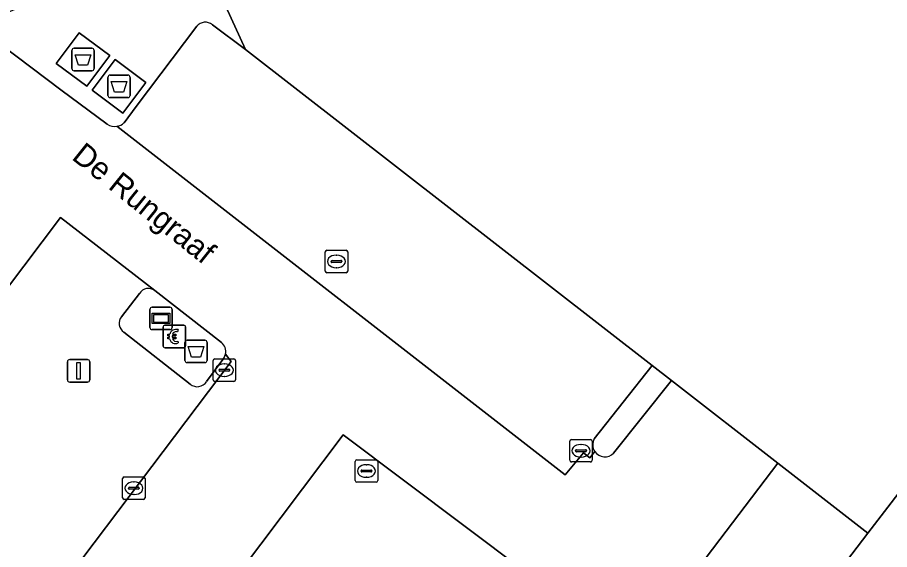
# Model space of a CAD drawing. Extents: x 160663 to 161506, y 382245 to 383291.
# Drawn here: x 161027.46 to 161066.28, y 382872.88 to 382896.55 of the extents above; entities that cross this region are included whole.
import ezdxf

# ---------------------------------------------------------------- set-up
doc = ezdxf.new("R2010")
doc.units = 0
for name, color, linetype in [('IMGEO_Afval_apart_plaats', 7, 'Continuous'), ('IMGEO_Afvalbak', 7, 'Continuous'), ('IMGEO_Betaalautomaat', 7, 'Continuous'), ('IMGEO_Erf', 7, 'Continuous'), ('IMGEO_Hek', 7, 'Continuous'), ('IMGEO_Kolk', 7, 'Continuous'), ('IMGEO_Lichtmast', 7, 'Continuous'), ('IMGEO_Muur', 7, 'Continuous'), ('IMGEO_Openbare_ruimte_label', 7, 'Continuous'), ('IMGEO_Parkeervlak_open', 7, 'Continuous'), ('IMGEO_Rijbaan_lokaal_open', 7, 'Continuous'), ('IMGEO_Rioolput', 7, 'Continuous'), ('IMGEO_Verkeerseiland_open', 7, 'Continuous'), ('IMGEO_Voetpad_gesloten', 7, 'Continuous'), ('IMGEO_Voetpad_open', 7, 'Continuous'), ('IMGEO_Wegwijzer', 7, 'Continuous')]:
    doc.layers.add(name, color=color, linetype=linetype)

msp = doc.modelspace()

# ---------------------------------------------------------------- linework, layer by layer
at = {"layer": 'IMGEO_Afval_apart_plaats'}
for p, q in [((161029.884, 382894.283), (161029.884, 382895.083)), ((161029.884, 382895.083), (161029.884, 382894.283)), ((161029.984, 382895.183), (161030.774, 382895.183)), ((161030.774, 382895.183), (161029.984, 382895.183)), ((161030.874, 382895.083), (161030.874, 382894.283)), ((161030.874, 382894.283), (161030.874, 382895.083)), ((161030.774, 382894.183), (161029.984, 382894.183)), ((161029.984, 382894.183), (161030.774, 382894.183)), ((161031.486, 382893.086), (161031.486, 382893.886)), ((161031.486, 382893.886), (161031.486, 382893.086)), ((161031.586, 382893.986), (161032.376, 382893.986)), ((161032.376, 382893.986), (161031.586, 382893.986)), ((161032.476, 382893.886), (161032.476, 382893.086)), ((161032.476, 382893.086), (161032.476, 382893.886)), ((161032.376, 382892.986), (161031.586, 382892.986)), ((161031.586, 382892.986), (161032.376, 382892.986))]:
    msp.add_line(p, q, dxfattribs=at)
for points in [[(161030.027, 382894.897), (161030.731, 382894.897), (161030.582, 382894.427), (161030.176, 382894.427), (161030.027, 382894.897)], [(161031.629, 382893.7), (161032.333, 382893.7), (161032.184, 382893.23), (161031.778, 382893.23), (161031.629, 382893.7)]]:
    msp.add_lwpolyline(points, dxfattribs=at)
for centre, start, end in [((161029.984, 382895.083), 90, 180), ((161029.984, 382895.083), 90, 180), ((161030.774, 382895.083), 0, 90), ((161030.774, 382895.083), 360, 90), ((161029.984, 382894.283), 180, 270), ((161029.984, 382894.283), 180, 270), ((161030.774, 382894.283), 270, 0), ((161030.774, 382894.283), 270, 0), ((161031.586, 382893.886), 90, 180), ((161031.586, 382893.886), 90, 180), ((161032.376, 382893.886), 0, 90), ((161032.376, 382893.886), 360, 90), ((161031.586, 382893.086), 180, 270), ((161031.586, 382893.086), 180, 270), ((161032.376, 382893.086), 270, 0), ((161032.376, 382893.086), 270, 0)]:
    msp.add_arc(centre, 0.1, start, end, dxfattribs=at)
at = {"layer": 'IMGEO_Afvalbak'}
for p, q in [((161035.015, 382882.198), (161035.805, 382882.198)), ((161035.805, 382882.198), (161035.015, 382882.198)), ((161034.915, 382881.298), (161034.915, 382882.098)), ((161034.915, 382882.098), (161034.915, 382881.298)), ((161035.905, 382882.098), (161035.905, 382881.298)), ((161035.905, 382881.298), (161035.905, 382882.098)), ((161035.805, 382881.198), (161035.015, 382881.198)), ((161035.015, 382881.198), (161035.805, 382881.198))]:
    msp.add_line(p, q, dxfattribs=at)
msp.add_lwpolyline([(161035.058, 382881.912), (161035.762, 382881.912), (161035.613, 382881.442), (161035.207, 382881.442), (161035.058, 382881.912)], dxfattribs=at)
for centre, start, end in [((161035.015, 382882.098), 90, 180), ((161035.015, 382882.098), 90, 180), ((161035.805, 382882.098), 0, 90), ((161035.805, 382882.098), 360, 90), ((161035.015, 382881.298), 180, 270), ((161035.015, 382881.298), 180, 270), ((161035.805, 382881.298), 270, 0), ((161035.805, 382881.298), 270, 0)]:
    msp.add_arc(centre, 0.1, start, end, dxfattribs=at)
at = {"layer": 'IMGEO_Betaalautomaat'}
for p, q in [((161033.948, 382881.936), (161033.948, 382882.777)), ((161033.948, 382882.777), (161033.948, 382881.936)), ((161034.023, 382882.86), (161034.864, 382882.86)), ((161034.864, 382882.86), (161034.023, 382882.86)), ((161034.61, 382882.665), (161034.593, 382882.565)), ((161034.947, 382882.786), (161034.947, 382881.945)), ((161034.947, 382881.945), (161034.947, 382882.786)), ((161034.231, 382882.324), (161034.231, 382882.392)), ((161034.352, 382882.392), (161034.352, 382882.324)), ((161034.597, 382882.159), (161034.619, 382882.072)), ((161034.873, 382881.861), (161034.032, 382881.861)), ((161034.032, 382881.861), (161034.873, 382881.861))]:
    msp.add_line(p, q, dxfattribs=at)
for points in [[(161034.231, 382882.392), (161034.162, 382882.392), (161034.162, 382882.461), (161034.241, 382882.461)], [(161034.236, 382882.255), (161034.162, 382882.255), (161034.162, 382882.324), (161034.231, 382882.324)], [(161034.363, 382882.461), (161034.51, 382882.461), (161034.51, 382882.392), (161034.352, 382882.392)], [(161034.352, 382882.324), (161034.51, 382882.324), (161034.51, 382882.255), (161034.366, 382882.255)]]:
    msp.add_lwpolyline(points, dxfattribs=at)
for centre, radius, start, end in [((161034.026, 382882.783), 0.0779, 92.4484, 184.2845), ((161034.026, 382882.783), 0.0779, 92.4484, 184.2845), ((161034.524, 382882.385), 0.293, 73.014, 165.0139), ((161034.53, 382882.398), 0.179, 69.3236, 159.5683), ((161034.87, 382882.783), 0.0779, 2.4484, 94.2845), ((161034.87, 382882.783), 0.0779, 2.4484, 94.2845), ((161034.497, 382882.31), 0.267, 191.8096, 297.0389), ((161034.53, 382882.325), 0.179, 202.7625, 291.8693), ((161034.026, 382881.939), 0.0779, 182.4484, 274.2845), ((161034.026, 382881.939), 0.0779, 182.4484, 274.2845), ((161034.87, 382881.939), 0.0779, 272.4484, 4.2845), ((161034.87, 382881.939), 0.0779, 272.4484, 4.2845)]:
    msp.add_arc(centre, radius, start, end, dxfattribs=at)
at = {"layer": 'IMGEO_Erf'}
for points in [[(161089.483, 382914.349), (161092.898, 382902.175), (161085.204, 382899.284), (161075.956, 382887.48), (161079.159, 382884.954), (161077.254, 382882.517), (161074.193, 382884.816), (161073.985, 382884.972), (161071.411, 382881.518), (161069.846, 382879.509), (161065.315, 382873.613), (161053.485, 382858.1), (161064.499, 382849.638), (161050.562, 382831.481)], [(161066.844, 382906.549), (161059.078, 382905.378), (161058.094, 382904.602), (161058.28, 382904.367), (161057.902, 382904.07), (161050.966, 382903.262), (161046.544, 382901.321), (161044.474, 382906.103), (161040.595, 382904.367), (161041.864, 382901.513), (161040.011, 382900.714), (161037.932, 382905.534), (161033.8, 382903.661), (161035.229, 382900.358), (161037.616, 382895.122), (161055.707, 382881.074), (161056.574, 382880.401), (161061.31, 382876.723), (161065.315, 382873.613), (161069.846, 382879.509)]]:
    msp.add_lwpolyline(points, dxfattribs=at)
at = {"layer": 'IMGEO_Hek'}
msp.add_lwpolyline([(161069.846, 382879.509), (161065.315, 382873.613)], dxfattribs=at)
at = {"layer": 'IMGEO_Kolk'}
for p, q in [((161041.162, 382885.274), (161041.162, 382886.126)), ((161041.237, 382886.2), (161042.089, 382886.2)), ((161042.163, 382886.126), (161042.163, 382885.274)), ((161041.421, 382885.694), (161041.421, 382885.706)), ((161041.859, 382885.657), (161041.461, 382885.657)), ((161041.464, 382885.743), (161041.862, 382885.743)), ((161041.65, 382885.98), (161041.675, 382885.98)), ((161041.905, 382885.706), (161041.905, 382885.694)), ((161041.673, 382885.42), (161041.648, 382885.42)), ((161042.089, 382885.2), (161041.237, 382885.2)), ((161036.248, 382881.364), (161037.1, 382881.364)), ((161036.173, 382880.438), (161036.173, 382881.29)), ((161036.661, 382881.144), (161036.686, 382881.144)), ((161037.174, 382881.29), (161037.174, 382880.438)), ((161036.432, 382880.858), (161036.432, 382880.87)), ((161036.87, 382880.821), (161036.472, 382880.821)), ((161036.475, 382880.907), (161036.873, 382880.907)), ((161036.684, 382880.584), (161036.659, 382880.584)), ((161036.916, 382880.87), (161036.916, 382880.858)), ((161037.1, 382880.364), (161036.248, 382880.364)), ((161052.045, 382876.853), (161052.045, 382877.705)), ((161052.12, 382877.779), (161052.972, 382877.779)), ((161052.533, 382877.559), (161052.558, 382877.559)), ((161053.046, 382877.705), (161053.046, 382876.853)), ((161052.304, 382877.273), (161052.304, 382877.285)), ((161052.742, 382877.236), (161052.344, 382877.236)), ((161052.347, 382877.322), (161052.745, 382877.322)), ((161052.788, 382877.285), (161052.788, 382877.273)), ((161052.972, 382876.779), (161052.12, 382876.779)), ((161052.556, 382876.999), (161052.531, 382876.999)), ((161032.144, 382875.186), (161032.144, 382876.038)), ((161032.219, 382876.112), (161033.071, 382876.112)), ((161033.145, 382876.038), (161033.145, 382875.186)), ((161032.403, 382875.606), (161032.403, 382875.618)), ((161032.841, 382875.569), (161032.443, 382875.569)), ((161032.446, 382875.655), (161032.844, 382875.655)), ((161032.632, 382875.892), (161032.657, 382875.892)), ((161032.887, 382875.618), (161032.887, 382875.606)), ((161032.655, 382875.332), (161032.63, 382875.332)), ((161033.071, 382875.112), (161032.219, 382875.112))]:
    msp.add_line(p, q, dxfattribs=at)
for points in [[(161041.162, 382885.274), (161041.162, 382886.126)], [(161041.237, 382886.2), (161042.089, 382886.2)], [(161042.163, 382886.126), (161042.163, 382885.274)], [(161042.089, 382885.2), (161041.237, 382885.2)], [(161036.248, 382881.364), (161037.1, 382881.364)], [(161036.173, 382880.438), (161036.173, 382881.29)], [(161037.174, 382881.29), (161037.174, 382880.438)], [(161037.1, 382880.364), (161036.248, 382880.364)], [(161052.045, 382876.853), (161052.045, 382877.705)], [(161052.12, 382877.779), (161052.972, 382877.779)], [(161053.046, 382877.705), (161053.046, 382876.853)], [(161052.972, 382876.779), (161052.12, 382876.779)], [(161032.144, 382875.186), (161032.144, 382876.038)], [(161032.219, 382876.112), (161033.071, 382876.112)], [(161033.145, 382876.038), (161033.145, 382875.186)], [(161033.071, 382875.112), (161032.219, 382875.112)]]:
    msp.add_lwpolyline(points, dxfattribs=at)
for centre, radius, start, end in [((161041.239, 382886.124), 0.0765, 91.552, 178.448), ((161041.239, 382886.124), 0.0765, 91.552, 178.448), ((161042.087, 382886.124), 0.0765, 1.552, 88.448), ((161042.087, 382886.124), 0.0765, 1.552, 88.448), ((161041.461, 382885.703), 0.0403, 85.8775, 175.7526), ((161041.458, 382885.693), 0.0366, 178.938, 274.7102), ((161041.862, 382885.7), 0.043, 264.8664, 352.4533), ((161041.866, 382885.705), 0.0386, 1.7309, 96.639), ((161041.239, 382885.276), 0.0765, 181.552, 268.448), ((161041.239, 382885.276), 0.0765, 181.552, 268.448), ((161042.087, 382885.276), 0.0765, 271.552, 358.448), ((161042.087, 382885.276), 0.0765, 271.552, 358.448), ((161036.25, 382881.288), 0.0765, 91.552, 178.448), ((161036.25, 382881.288), 0.0765, 91.552, 178.448), ((161037.098, 382881.288), 0.0765, 1.552, 88.448), ((161037.098, 382881.288), 0.0765, 1.552, 88.448), ((161036.472, 382880.867), 0.0403, 85.8775, 175.7526), ((161036.469, 382880.857), 0.0366, 178.938, 274.7102), ((161036.873, 382880.864), 0.043, 264.8664, 352.4533), ((161036.877, 382880.869), 0.0386, 1.7309, 96.639), ((161036.25, 382880.44), 0.0765, 181.552, 268.448), ((161036.25, 382880.44), 0.0765, 181.552, 268.448), ((161037.098, 382880.44), 0.0765, 271.552, 358.448), ((161037.098, 382880.44), 0.0765, 271.552, 358.448), ((161052.122, 382877.703), 0.0765, 91.552, 178.448), ((161052.122, 382877.703), 0.0765, 91.552, 178.448), ((161052.97, 382877.703), 0.0765, 1.552, 88.448), ((161052.97, 382877.703), 0.0765, 1.552, 88.448), ((161052.344, 382877.282), 0.0403, 85.8775, 175.7526), ((161052.341, 382877.272), 0.0366, 178.938, 274.7102), ((161052.745, 382877.279), 0.043, 264.8664, 352.4533), ((161052.749, 382877.284), 0.0386, 1.7309, 96.639), ((161052.122, 382876.855), 0.0765, 181.552, 268.448), ((161052.122, 382876.855), 0.0765, 181.552, 268.448), ((161052.97, 382876.855), 0.0765, 271.552, 358.448), ((161052.97, 382876.855), 0.0765, 271.552, 358.448), ((161032.221, 382876.036), 0.0765, 91.552, 178.448), ((161032.221, 382876.036), 0.0765, 91.552, 178.448), ((161033.069, 382876.036), 0.0765, 1.552, 88.448), ((161033.069, 382876.036), 0.0765, 1.552, 88.448), ((161032.443, 382875.615), 0.0403, 85.8775, 175.7526), ((161032.44, 382875.605), 0.0366, 178.938, 274.7102), ((161032.844, 382875.612), 0.043, 264.8664, 352.4533), ((161032.848, 382875.617), 0.0386, 1.7309, 96.639), ((161032.221, 382875.188), 0.0765, 181.552, 268.448), ((161032.221, 382875.188), 0.0765, 181.552, 268.448), ((161033.069, 382875.188), 0.0765, 271.552, 358.448), ((161033.069, 382875.188), 0.0765, 271.552, 358.448)]:
    msp.add_arc(centre, radius, start, end, dxfattribs=at)
for centre, major_axis, ratio, start_param, end_param in [((161041.649, 382885.7), (-0.387, 0.002), 0.722429, 4.712389, 7.853982), ((161041.674, 382885.7), (-0.39, 0.002), 0.717154, 1.570796, 4.712389), ((161036.66, 382880.864), (-0.387, 0.002), 0.722429, 4.712389, 7.853982), ((161036.685, 382880.864), (-0.39, 0.002), 0.717154, 1.570796, 4.712389), ((161052.532, 382877.279), (-0.387, 0.002), 0.722429, 4.712389, 7.853982), ((161052.557, 382877.279), (-0.39, 0.002), 0.717154, 1.570796, 4.712389), ((161032.631, 382875.612), (-0.387, 0.002), 0.722429, 4.712389, 7.853982), ((161032.656, 382875.612), (-0.39, 0.002), 0.717154, 1.570796, 4.712389)]:
    msp.add_ellipse(centre, major_axis=major_axis, ratio=ratio, start_param=start_param, end_param=end_param, dxfattribs=at)
at = {"layer": 'IMGEO_Lichtmast'}
for p, q in [((161029.789, 382881.334), (161030.579, 382881.334)), ((161030.579, 382881.334), (161029.789, 382881.334)), ((161029.689, 382880.434), (161029.689, 382881.234)), ((161029.689, 382881.234), (161029.689, 382880.434)), ((161030.679, 382881.234), (161030.679, 382880.434)), ((161030.679, 382880.434), (161030.679, 382881.234)), ((161030.579, 382880.334), (161029.789, 382880.334)), ((161029.789, 382880.334), (161030.579, 382880.334))]:
    msp.add_line(p, q, dxfattribs=at)
msp.add_lwpolyline([(161030.109, 382881.209), (161030.259, 382881.209), (161030.259, 382880.459), (161030.109, 382880.459), (161030.109, 382881.209)], dxfattribs=at)
for centre, start, end in [((161029.789, 382881.234), 90, 180), ((161029.789, 382881.234), 90, 180), ((161030.579, 382881.234), 0, 90), ((161030.579, 382881.234), 360, 90), ((161029.789, 382880.434), 180, 270), ((161029.789, 382880.434), 180, 270), ((161030.579, 382880.434), 270, 0), ((161030.579, 382880.434), 270, 0)]:
    msp.add_arc(centre, 0.1, start, end, dxfattribs=at)
at = {"layer": 'IMGEO_Muur'}
for points in [[(161037.616, 382895.122), (161035.229, 382900.358)], [(161055.707, 382881.074), (161037.616, 382895.122)], [(161061.31, 382876.723), (161065.315, 382873.613)]]:
    msp.add_lwpolyline(points, dxfattribs=at)
at = {"layer": 'IMGEO_Parkeervlak_open'}
for points in [[(161035.441, 382896.16), (161032.752, 382892.592), (161032.206, 382891.868)], [(161037.616, 382895.122), (161036.145, 382896.226)], [(161053.138, 382877.809), (161055.707, 382881.074), (161037.616, 382895.122)], [(161031.89, 382891.715), (161051.844, 382876.215), (161052.657, 382877.184), (161052.932, 382876.971), (161053.162, 382877.241)], [(161033.577, 382884.405), (161029.375, 382887.651), (161006.741, 382857.643), (161014.674, 382851.774), (161036.973, 382881.256), (161036.728, 382881.578), (161036.656, 382881.396), (161035.877, 382880.352)], [(161032.088, 382883.243), (161032.897, 382884.273)], [(161035.156, 382880.239), (161032.196, 382882.556)]]:
    msp.add_lwpolyline(points, dxfattribs=at)
msp.add_lwpolyline([(161026.197, 382840.33), (161050.071, 382871.893), (161041.959, 382877.99), (161018.147, 382846.412)], close=True, dxfattribs=at)
for centre, radius, start, end in [((161035.826, 382895.842), 0.499, 50.2931, 140.4186), ((161031.785, 382892.334), 0.628, 279.5962, 312.0742), ((161033.296, 382884.035), 0.465, 52.7846, 149.1864), ((161032.463, 382882.95), 0.476, 142.0313, 235.8369), ((161035.467, 382880.614), 0.487, 230.3779, 327.4368), ((161053.607, 382877.544), 0.539, 150.5886, 214.2504)]:
    msp.add_arc(centre, radius, start, end, dxfattribs=at)
at = {"layer": 'IMGEO_Rijbaan_lokaal_open'}
for points in [[(161031.451, 382891.801), (161029.397, 382893.332), (161021.429, 382899.354), (161021.072, 382900.069), (161015.099, 382897.458), (161014.607, 382897.256), (161019.667, 382893.047), (161023.576, 382889.795), (161000, 382858.557), (160999.119, 382857.39), (161000, 382856.514), (161009.04, 382847.522), (161015.219, 382842.521), (161017.015, 382841.125), (161024.581, 382835.124), (161027.763, 382832.6), (161061.31, 382876.723)], [(161053.162, 382877.241), (161052.932, 382876.971), (161052.657, 382877.184), (161051.844, 382876.215), (161031.89, 382891.715)], [(161014.674, 382851.774), (161006.741, 382857.643), (161029.375, 382887.651), (161033.577, 382884.405), (161036.539, 382882.101)], [(161036.728, 382881.578), (161036.973, 382881.256), (161014.674, 382851.774)], [(161061.31, 382876.723), (161056.574, 382880.401), (161053.994, 382877.175)]]:
    msp.add_lwpolyline(points, dxfattribs=at)
msp.add_lwpolyline([(161041.959, 382877.99), (161050.071, 382871.893), (161026.197, 382840.33), (161018.147, 382846.412)], close=True, dxfattribs=at)
for centre, radius, start, end in [((161031.785, 382892.341), 0.635, 238.2925, 279.5398), ((161036.199, 382881.682), 0.539, 348.8379, 50.8995), ((161053.605, 382877.546), 0.538, 214.5539, 316.3749)]:
    msp.add_arc(centre, radius, start, end, dxfattribs=at)
at = {"layer": 'IMGEO_Rioolput'}
for p, q in [((161042.496, 382875.952), (161042.496, 382876.804)), ((161042.571, 382876.878), (161043.423, 382876.878)), ((161043.497, 382876.804), (161043.497, 382875.952)), ((161042.755, 382876.372), (161042.755, 382876.384)), ((161043.193, 382876.335), (161042.795, 382876.335)), ((161042.798, 382876.421), (161043.196, 382876.421)), ((161042.984, 382876.658), (161043.009, 382876.658)), ((161043.239, 382876.384), (161043.239, 382876.372)), ((161043.007, 382876.098), (161042.982, 382876.098)), ((161043.423, 382875.878), (161042.571, 382875.878))]:
    msp.add_line(p, q, dxfattribs=at)
for points in [[(161042.496, 382875.952), (161042.496, 382876.804)], [(161042.571, 382876.878), (161043.423, 382876.878)], [(161043.497, 382876.804), (161043.497, 382875.952)], [(161043.423, 382875.878), (161042.571, 382875.878)]]:
    msp.add_lwpolyline(points, dxfattribs=at)
for centre, radius, start, end in [((161042.573, 382876.802), 0.0765, 91.552, 178.448), ((161042.573, 382876.802), 0.0765, 91.552, 178.448), ((161043.421, 382876.802), 0.0765, 1.552, 88.448), ((161043.421, 382876.802), 0.0765, 1.552, 88.448), ((161042.795, 382876.381), 0.0403, 85.8775, 175.7526), ((161042.792, 382876.371), 0.0366, 178.938, 274.7102), ((161043.196, 382876.378), 0.043, 264.8664, 352.4533), ((161043.2, 382876.383), 0.0386, 1.7309, 96.639), ((161042.573, 382875.954), 0.0765, 181.552, 268.448), ((161042.573, 382875.954), 0.0765, 181.552, 268.448), ((161043.421, 382875.954), 0.0765, 271.552, 358.448), ((161043.421, 382875.954), 0.0765, 271.552, 358.448)]:
    msp.add_arc(centre, radius, start, end, dxfattribs=at)
for centre, major_axis, ratio, start_param, end_param in [((161042.983, 382876.378), (-0.387, 0.002), 0.722429, 4.712389, 7.853982), ((161043.008, 382876.378), (-0.39, 0.002), 0.717154, 1.570796, 4.712389)]:
    msp.add_ellipse(centre, major_axis=major_axis, ratio=ratio, start_param=start_param, end_param=end_param, dxfattribs=at)
at = {"layer": 'IMGEO_Verkeerseiland_open'}
for points in [[(161032.897, 382884.273), (161032.088, 382883.243)], [(161036.539, 382882.101), (161033.577, 382884.405)], [(161032.196, 382882.556), (161035.156, 382880.239)], [(161035.877, 382880.352), (161036.656, 382881.396), (161036.728, 382881.578)], [(161053.994, 382877.175), (161056.574, 382880.401), (161055.707, 382881.074), (161053.138, 382877.809)]]:
    msp.add_lwpolyline(points, dxfattribs=at)
for centre, radius, start, end in [((161033.296, 382884.035), 0.465, 52.7846, 149.1864), ((161032.463, 382882.95), 0.476, 142.0313, 235.8369), ((161036.199, 382881.682), 0.539, 348.8379, 50.8995), ((161035.467, 382880.614), 0.487, 230.3779, 327.4368), ((161053.607, 382877.544), 0.539, 150.5886, 214.2504), ((161053.605, 382877.546), 0.538, 214.5539, 316.3749)]:
    msp.add_arc(centre, radius, start, end, dxfattribs=at)
at = {"layer": 'IMGEO_Voetpad_gesloten'}
for points in [[(161031.569, 382894.855), (161030.207, 382895.873), (161029.189, 382894.511), (161030.551, 382893.493)], [(161033.171, 382893.658), (161031.809, 382894.675), (161030.791, 382893.314), (161032.153, 382892.296)]]:
    msp.add_lwpolyline(points, close=True, dxfattribs=at)
at = {"layer": 'IMGEO_Voetpad_open'}
for points in [[(161035.229, 382900.358), (161027.01, 382896.764), (161024.827, 382901.808), (161023.07, 382901.081), (161021.758, 382900.364), (161021.072, 382900.069), (161021.429, 382899.354), (161029.397, 382893.332), (161031.451, 382891.801)], [(161036.145, 382896.226), (161037.616, 382895.122), (161035.229, 382900.358)], [(161032.206, 382891.868), (161032.752, 382892.592), (161035.441, 382896.16)]]:
    msp.add_lwpolyline(points, dxfattribs=at)
for points in [[(161031.569, 382894.855), (161030.551, 382893.493), (161029.189, 382894.511), (161030.207, 382895.873)], [(161033.171, 382893.658), (161032.153, 382892.296), (161030.791, 382893.314), (161031.809, 382894.675)], [(161052.966, 382858.403), (161053.444, 382858.047), (161053.485, 382858.1), (161065.315, 382873.613), (161061.31, 382876.723), (161027.763, 382832.6), (161031.709, 382829.469), (161034.089, 382832.61), (161033.688, 382832.928)]]:
    msp.add_lwpolyline(points, close=True, dxfattribs=at)
for centre, radius, start, end in [((161035.826, 382895.842), 0.499, 50.2931, 140.4186), ((161031.785, 382892.334), 0.628, 279.5962, 312.0742), ((161031.785, 382892.341), 0.635, 238.2925, 279.5398)]:
    msp.add_arc(centre, radius, start, end, dxfattribs=at)
at = {"layer": 'IMGEO_Wegwijzer'}
for p, q in [((161033.456, 382883.665), (161034.246, 382883.665)), ((161034.246, 382883.665), (161033.456, 382883.665)), ((161033.356, 382882.765), (161033.356, 382883.565)), ((161033.356, 382883.565), (161033.356, 382882.765)), ((161034.346, 382883.565), (161034.346, 382882.765)), ((161034.346, 382882.765), (161034.346, 382883.565)), ((161034.246, 382882.665), (161033.456, 382882.665)), ((161033.456, 382882.665), (161034.246, 382882.665))]:
    msp.add_line(p, q, dxfattribs=at)
for points in [[(161033.457, 382883.397), (161034.245, 382883.397), (161034.245, 382882.933), (161033.457, 382882.933), (161033.457, 382883.397)], [(161033.522, 382883.332), (161033.522, 382882.998), (161034.18, 382882.998), (161034.18, 382883.332), (161033.522, 382883.332)]]:
    msp.add_lwpolyline(points, dxfattribs=at)
for centre, start, end in [((161033.456, 382883.565), 90, 180), ((161033.456, 382883.565), 90, 180), ((161034.246, 382883.565), 0, 90), ((161034.246, 382883.565), 360, 90), ((161033.456, 382882.765), 180, 270), ((161033.456, 382882.765), 180, 270), ((161034.246, 382882.765), 270, 0), ((161034.246, 382882.765), 270, 0)]:
    msp.add_arc(centre, 0.1, start, end, dxfattribs=at)

# ---------------------------------------------------------------- texts
at = {"layer": 'IMGEO_Openbare_ruimte_label'}
msp.add_text('De Rungraaf', height=1, rotation=321.2507, dxfattribs=at).set_placement((161029.833, 382890.278))

doc.saveas('drawing.dxf')
